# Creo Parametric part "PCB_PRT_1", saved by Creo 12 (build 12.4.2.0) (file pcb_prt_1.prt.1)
Units: Custom; MM, KILOGRAM, SECS

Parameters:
  PTC_WM_ITERATION = "0"
  PTC_WM_VERSION = "-.0"
  PTC_WM_LIFECYCLE_STATE = "In Work"
  PTC_WM_LIFECYCLE = "MO_CADDocument"
  PTC_WM_CREATED_BY = "Maximilian Roepper (Z0017RMS: MO)"
  PTC_WM_CREATED_ON = "18-Sep-26 11:36:42 AM"
  PTC_WM_MODIFIED_BY = "Maximilian Roepper (Z0017RMS: MO)"
  PTC_WM_MODIFIED_ON = "18-Sep-26 11:36:46 AM"
  PDMLINKNUMBER = "PDM000071455134"
  PTC_WM_NAME = "pcb_prt_1.prt"
  PTC_WM_NUMBER = "PDM000071455134"

Other parameters: WEIGHT, WEIGHT_FACTOR, WEIGHT_ADD, _MASS_TEMP, _DIFF_TEMP, MC_ERRORS, SUPPLIER

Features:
  1. coordinate system
  2. datum plane "PRT_YZ"
  3. datum plane "PRT_XY"
  4. datum plane "PRT_XZ"
  5. coordinate system
  6. datum axis
  7. datum axis
  8. datum axis
  9. coordinate system
  10. imported feature
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
Other named items: PRT, SIEMENS_MO, DRW_VIEW_ORG, PRT_X, PRT_Y, PRT_Z, CS0, ROUGH_GROB

Layers: 00_STD_CSYS-KSYS, 01_STD_PLANES-EBENEN, 02_STD_AXES-ACHSEN, 03_STD_CSYS-KSYS, 24_IMPORT_FEAT-IMPORT_KE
